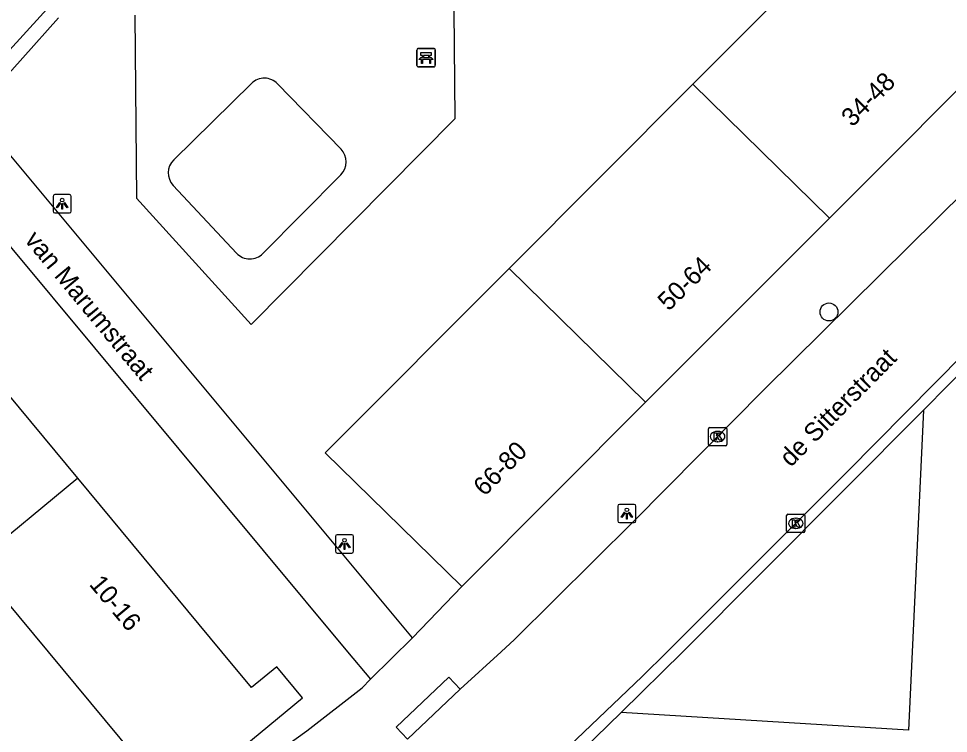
# Model space of a CAD drawing. Extents: x 159888 to 160757, y 384031 to 384746.
# Drawn here: x 160339 to 160389.7, y 384245.5 to 384284.5 of the extents above; entities that cross this region are included whole.
import ezdxf

# ---------------------------------------------------------------- set-up
doc = ezdxf.new("R2010")
doc.units = 0
for name, color, linetype in [('IMGEO_Bank', 7, 'Continuous'), ('IMGEO_Boom', 7, 'Continuous'), ('IMGEO_Kolk', 7, 'Continuous'), ('IMGEO_Lichtpunt', 7, 'Continuous'), ('IMGEO_Openbare_ruimte_label', 7, 'Continuous'), ('IMGEO_Pand', 7, 'Continuous'), ('IMGEO_Pand_nummerreeks', 7, 'Continuous'), ('IMGEO_Rijbaan_lokaal_open', 7, 'Continuous'), ('IMGEO_Voetpad_halfverhard', 7, 'Continuous'), ('IMGEO_Voetpad_open', 7, 'Continuous')]:
    doc.layers.add(name, color=color, linetype=linetype)

msp = doc.modelspace()

# ---------------------------------------------------------------- linework, layer by layer
at = {"layer": 'IMGEO_Bank'}
for p, q in [((160360.748, 384281.983), (160360.748, 384282.824)), ((160360.748, 384282.824), (160360.748, 384281.983)), ((160360.823, 384282.908), (160361.664, 384282.908)), ((160361.664, 384282.908), (160360.823, 384282.908)), ((160361.748, 384282.833), (160361.748, 384281.992)), ((160361.748, 384281.992), (160361.748, 384282.833)), ((160361.445, 384282.306), (160361.052, 384282.306)), ((160361.057, 384282.414), (160361.057, 384282.52)), ((160361.101, 384282.52), (160361.101, 384282.414)), ((160361.389, 384282.526), (160361.107, 384282.526)), ((160361.107, 384282.408), (160361.389, 384282.408)), ((160361.395, 384282.414), (160361.395, 384282.52)), ((160361.439, 384282.52), (160361.439, 384282.414)), ((160361.673, 384281.908), (160360.832, 384281.908)), ((160360.832, 384281.908), (160361.673, 384281.908))]:
    msp.add_line(p, q, dxfattribs=at)
for points in [[(160360.995, 384282.306), (160360.853, 384282.306), (160360.965, 384282.408), (160361.051, 384282.408)], [(160361.051, 384282.526), (160360.965, 384282.526), (160360.965, 384282.687), (160361.528, 384282.687), (160361.528, 384282.526), (160361.445, 384282.526)], [(160361.045, 384282.299), (160361.045, 384282.092), (160361.002, 384282.092), (160361.002, 384282.299)], [(160361.445, 384282.408), (160361.528, 384282.408), (160361.64, 384282.306), (160361.501, 384282.306)], [(160361.495, 384282.299), (160361.495, 384282.092), (160361.451, 384282.092), (160361.451, 384282.299)]]:
    msp.add_lwpolyline(points, dxfattribs=at)
for centre, radius, start, end in [((160360.826, 384282.83), 0.0779, 92.4484, 184.2845), ((160360.826, 384282.83), 0.0779, 92.4484, 184.2845), ((160361.67, 384282.83), 0.0779, 2.4484, 94.2845), ((160361.67, 384282.83), 0.0779, 2.4484, 94.2845), ((160360.995, 384282.299), 0.00671, 2.8957, 87.1043), ((160361.052, 384282.299), 0.00671, 92.8957, 177.1043), ((160361.05, 384282.519), 0.00671, 2.8957, 87.1043), ((160361.05, 384282.415), 0.00671, 272.8957, 357.1043), ((160361.107, 384282.519), 0.00671, 92.8957, 177.1043), ((160361.107, 384282.415), 0.00671, 182.8957, 267.1043), ((160361.389, 384282.519), 0.00671, 2.8957, 87.1043), ((160361.389, 384282.415), 0.00671, 272.8957, 357.1043), ((160361.446, 384282.519), 0.00671, 92.8957, 177.1043), ((160361.446, 384282.415), 0.00671, 182.8957, 267.1043), ((160361.444, 384282.299), 0.00671, 2.8957, 87.1043), ((160361.501, 384282.299), 0.00671, 92.8957, 177.1043), ((160360.826, 384281.986), 0.0779, 182.4484, 274.2845), ((160360.826, 384281.986), 0.0779, 182.4484, 274.2845), ((160361.67, 384281.986), 0.0779, 272.4484, 4.2845), ((160361.67, 384281.986), 0.0779, 272.4484, 4.2845)]:
    msp.add_arc(centre, radius, start, end, dxfattribs=at)
at = {"layer": 'IMGEO_Boom'}
msp.add_circle((160383.226, 384268.536), 0.489, dxfattribs=at)
at = {"layer": 'IMGEO_Kolk'}
for p, q in [((160376.649, 384261.31), (160376.649, 384262.162)), ((160376.724, 384262.236), (160377.576, 384262.236)), ((160377.137, 384262.016), (160377.162, 384262.016)), ((160377.65, 384262.162), (160377.65, 384261.31)), ((160377.576, 384261.236), (160376.724, 384261.236)), ((160377.16, 384261.456), (160377.135, 384261.456)), ((160380.991, 384257.501), (160381.843, 384257.501)), ((160380.916, 384256.575), (160380.916, 384257.427)), ((160381.404, 384257.281), (160381.429, 384257.281)), ((160381.917, 384257.427), (160381.917, 384256.575)), ((160381.843, 384256.501), (160380.991, 384256.501)), ((160381.427, 384256.721), (160381.402, 384256.721))]:
    msp.add_line(p, q, dxfattribs=at)
for points in [[(160376.649, 384261.31), (160376.649, 384262.162)], [(160376.724, 384262.236), (160377.576, 384262.236)], [(160377.65, 384262.162), (160377.65, 384261.31)], [(160376.97, 384261.936), (160377.093, 384261.936), (160377.093, 384261.785), (160377.223, 384261.936), (160377.387, 384261.936), (160377.241, 384261.785), (160377.394, 384261.536), (160377.242, 384261.536), (160377.157, 384261.7), (160377.093, 384261.633), (160377.093, 384261.536), (160376.97, 384261.536), (160376.97, 384261.936)], [(160377.576, 384261.236), (160376.724, 384261.236)], [(160380.991, 384257.501), (160381.843, 384257.501)], [(160380.916, 384256.575), (160380.916, 384257.427)], [(160381.237, 384257.201), (160381.36, 384257.201), (160381.36, 384257.05), (160381.49, 384257.201), (160381.654, 384257.201), (160381.508, 384257.05), (160381.661, 384256.801), (160381.509, 384256.801), (160381.424, 384256.965), (160381.36, 384256.898), (160381.36, 384256.801), (160381.237, 384256.801), (160381.237, 384257.201)], [(160381.917, 384257.427), (160381.917, 384256.575)], [(160381.843, 384256.501), (160380.991, 384256.501)]]:
    msp.add_lwpolyline(points, dxfattribs=at)
for centre, start, end in [((160376.726, 384262.16), 91.552, 178.448), ((160376.726, 384262.16), 91.552, 178.448), ((160377.574, 384262.16), 1.552, 88.448), ((160377.574, 384262.16), 1.552, 88.448), ((160376.726, 384261.312), 181.552, 268.448), ((160376.726, 384261.312), 181.552, 268.448), ((160377.574, 384261.312), 271.552, 358.448), ((160377.574, 384261.312), 271.552, 358.448), ((160380.993, 384257.425), 91.552, 178.448), ((160380.993, 384257.425), 91.552, 178.448), ((160381.841, 384257.425), 1.552, 88.448), ((160381.841, 384257.425), 1.552, 88.448), ((160380.993, 384256.577), 181.552, 268.448), ((160380.993, 384256.577), 181.552, 268.448), ((160381.841, 384256.577), 271.552, 358.448), ((160381.841, 384256.577), 271.552, 358.448)]:
    msp.add_arc(centre, 0.0765, start, end, dxfattribs=at)
for centre, major_axis, ratio, start_param, end_param in [((160377.136, 384261.736), (-0.387, 0.002), 0.722429, 4.712389, 7.853982), ((160377.161, 384261.736), (-0.39, 0.002), 0.717154, 1.570796, 4.712389), ((160381.403, 384257.001), (-0.387, 0.002), 0.722429, 4.712389, 7.853982), ((160381.428, 384257.001), (-0.39, 0.002), 0.717154, 1.570796, 4.712389)]:
    msp.add_ellipse(centre, major_axis=major_axis, ratio=ratio, start_param=start_param, end_param=end_param, dxfattribs=at)
at = {"layer": 'IMGEO_Lichtpunt'}
for p, q in [((160340.892, 384274.841), (160340.892, 384274.034)), ((160340.892, 384274.841), (160340.892, 384274.034)), ((160341.794, 384274.936), (160340.986, 384274.936)), ((160341.794, 384274.936), (160340.986, 384274.936)), ((160341.888, 384274.034), (160341.888, 384274.841)), ((160341.888, 384274.034), (160341.888, 384274.841)), ((160340.986, 384273.94), (160341.794, 384273.94)), ((160340.986, 384273.94), (160341.794, 384273.94)), ((160372.602, 384258.037), (160371.794, 384258.037)), ((160372.602, 384258.037), (160371.794, 384258.037)), ((160371.7, 384257.942), (160371.7, 384257.135)), ((160371.7, 384257.942), (160371.7, 384257.135)), ((160372.696, 384257.135), (160372.696, 384257.942)), ((160372.696, 384257.135), (160372.696, 384257.942)), ((160371.794, 384257.041), (160372.602, 384257.041)), ((160371.794, 384257.041), (160372.602, 384257.041)), ((160356.295, 384256.285), (160356.295, 384255.478)), ((160356.295, 384256.285), (160356.295, 384255.478)), ((160357.197, 384256.38), (160356.389, 384256.38)), ((160357.197, 384256.38), (160356.389, 384256.38)), ((160357.291, 384255.478), (160357.291, 384256.285)), ((160357.291, 384255.478), (160357.291, 384256.285)), ((160356.389, 384255.384), (160357.197, 384255.384)), ((160356.389, 384255.384), (160357.197, 384255.384))]:
    msp.add_line(p, q, dxfattribs=at)
for points in [[(160341.266, 384274.505), (160341.305, 384274.477), (160341.117, 384274.215), (160341.079, 384274.242), (160341.266, 384274.505)], [(160341.368, 384274.457), (160341.415, 384274.457), (160341.415, 384274.135), (160341.368, 384274.135), (160341.368, 384274.457)], [(160341.478, 384274.477), (160341.516, 384274.504), (160341.703, 384274.242), (160341.664, 384274.214), (160341.478, 384274.477)], [(160372.074, 384257.606), (160372.113, 384257.578), (160371.925, 384257.316), (160371.887, 384257.343), (160372.074, 384257.606)], [(160372.176, 384257.558), (160372.223, 384257.558), (160372.223, 384257.236), (160372.176, 384257.236), (160372.176, 384257.558)], [(160372.286, 384257.578), (160372.324, 384257.605), (160372.511, 384257.343), (160372.472, 384257.315), (160372.286, 384257.578)], [(160356.669, 384255.949), (160356.708, 384255.921), (160356.52, 384255.659), (160356.482, 384255.686), (160356.669, 384255.949)], [(160356.881, 384255.921), (160356.919, 384255.948), (160357.106, 384255.686), (160357.067, 384255.658), (160356.881, 384255.921)], [(160356.771, 384255.901), (160356.818, 384255.901), (160356.818, 384255.579), (160356.771, 384255.579), (160356.771, 384255.901)]]:
    msp.add_lwpolyline(points, dxfattribs=at)
for centre in [(160341.391, 384274.639), (160372.199, 384257.74), (160356.794, 384256.083)]:
    msp.add_circle(centre, 0.0994, dxfattribs=at)
for centre, start, end in [((160340.986, 384274.841), 90, 180), ((160340.986, 384274.841), 90, 180), ((160341.794, 384274.841), 0, 90), ((160341.794, 384274.841), 0, 90), ((160340.986, 384274.034), 180, 270), ((160340.986, 384274.034), 180, 270), ((160341.794, 384274.034), 270, 0), ((160341.794, 384274.034), 270, 360), ((160371.794, 384257.942), 90, 180), ((160371.794, 384257.942), 90, 180), ((160372.602, 384257.942), 0, 90), ((160372.602, 384257.942), 0, 90), ((160371.794, 384257.135), 180, 270), ((160371.794, 384257.135), 180, 270), ((160372.602, 384257.135), 270, 0), ((160372.602, 384257.135), 270, 360), ((160356.389, 384256.285), 90, 180), ((160356.389, 384256.285), 90, 180), ((160357.197, 384256.285), 0, 90), ((160357.197, 384256.285), 0, 90), ((160356.389, 384255.478), 180, 270), ((160356.389, 384255.478), 180, 270), ((160357.197, 384255.478), 270, 0), ((160357.197, 384255.478), 270, 360)]:
    msp.add_arc(centre, 0.0946, start, end, dxfattribs=at)
at = {"layer": 'IMGEO_Pand'}
for points in [[(160385.826, 384291.012), (160375.799, 384280.956)], [(160383.258, 384273.657), (160393.291, 384283.706)], [(160375.799, 384280.956), (160365.773, 384270.9)], [(160375.799, 384280.956), (160383.258, 384273.657)], [(160373.224, 384263.607), (160383.258, 384273.657)], [(160342.239, 384259.468), (160332.771, 384270.87), (160332.038, 384270.121), (160330.555, 384271.85), (160325.333, 384267.508), (160326.868, 384265.704), (160327.269, 384266.034), (160336.616, 384254.819)], [(160365.773, 384270.9), (160355.746, 384260.844), (160363.191, 384253.558)], [(160373.224, 384263.607), (160365.773, 384270.9)], [(160363.191, 384253.558), (160373.224, 384263.607)], [(160342.239, 384259.468), (160336.616, 384254.819)], [(160336.616, 384254.819), (160340.632, 384250), (160346.039, 384243.463), (160345.684, 384243.17), (160347.147, 384241.401), (160354.506, 384247.489), (160353.105, 384249.183), (160351.726, 384248.043), (160350.101, 384250), (160342.239, 384259.468)]]:
    msp.add_lwpolyline(points, dxfattribs=at)
at = {"layer": 'IMGEO_Rijbaan_lokaal_open'}
for points in [[(160319.303, 384267.551), (160320.163, 384268.187), (160325.613, 384272.322), (160329.833, 384275.348), (160333.576, 384278.079), (160335.984, 384279.983), (160336.104, 384280.105), (160336.716, 384280.731), (160338.331, 384282.617), (160345.01, 384289.972), (160361.399, 384308.557), (160367.398, 384315.345), (160372.06, 384320.608), (160386.091, 384336.349), (160387.995, 384338.559)], [(160415.801, 384300.405), (160412.696, 384297.247), (160409.504, 384293.847), (160396.973, 384281.372), (160379.726, 384264.338), (160372.559, 384257.094), (160366.063, 384250.659), (160365.342, 384250), (160363.109, 384247.959)], [(160346.326, 384226.816), (160346.553, 384226.989), (160354.699, 384232.863), (160360.784, 384237.351), (160361.189, 384237.649), (160363.689, 384239.781), (160364.647, 384240.62), (160366.673, 384242.576), (160373.037, 384248.641), (160374.399, 384250), (160384.224, 384259.805), (160390.609, 384266.27), (160401.354, 384277.085), (160418.41, 384294.276)], [(160363.109, 384247.959), (160360.237, 384245.231)]]:
    msp.add_lwpolyline(points, dxfattribs=at)
at = {"layer": 'IMGEO_Voetpad_halfverhard'}
for points in [[(160345.355, 384284.72), (160345.439, 384274.748), (160351.699, 384267.85), (160362.837, 384279.095), (160362.772, 384285.007)], [(160347.476, 384276.837), (160351.726, 384281.003)], [(160353.143, 384280.985), (160356.604, 384277.418)], [(160356.597, 384276.018), (160352.346, 384271.723)], [(160350.905, 384271.743), (160347.446, 384275.44)], [(160388.378, 384263.174), (160387.768, 384250), (160387.57, 384245.716), (160371.882, 384246.688)]]:
    msp.add_lwpolyline(points, dxfattribs=at)
for centre, radius, start, end in [((160352.426, 384280.287), 1.001, 44.1995, 134.3449), ((160355.885, 384276.722), 1.001, 315.3369, 44.0901), ((160348.174, 384276.123), 0.999, 134.376, 223.1635), ((160351.635, 384272.425), 0.999, 223.0474, 315.3623)]:
    msp.add_arc(centre, radius, start, end, dxfattribs=at)
at = {"layer": 'IMGEO_Voetpad_open'}
for points in [[(160336.483, 384279.562), (160337.275, 384280.219), (160341.199, 384284.583)], [(160360.504, 384250.764), (160336.483, 384279.562)], [(160333.927, 384277.642), (160356.959, 384250), (160358.209, 384248.5)], [(160388.378, 384263.174), (160391.104, 384265.938)], [(160371.882, 384246.688), (160375.258, 384250), (160388.378, 384263.174)], [(160360.504, 384250.764), (160363.191, 384253.558)], [(160358.209, 384248.5), (160360.504, 384250.764)], [(160340.225, 384235.253), (160354.731, 384245.687), (160357.767, 384248.02), (160358.209, 384248.5)], [(160363.109, 384247.959), (160362.49, 384248.612), (160359.618, 384245.884), (160360.237, 384245.231)], [(160369.777, 384244.623), (160371.882, 384246.688)]]:
    msp.add_lwpolyline(points, dxfattribs=at)

# ---------------------------------------------------------------- texts
at = {"layer": 'IMGEO_Openbare_ruimte_label'}
for s, rotation, p in [('van Marumstraat', 309.7249, (160339.298, 384272.441)), ('de Sitterstraat', 45.3242, (160381.139, 384260.027))]:
    msp.add_text(s, height=1, rotation=rotation, dxfattribs=at).set_placement(p)
at = {"layer": 'IMGEO_Pand_nummerreeks'}
for s, rotation, p in [('34-48', 45, (160384.502, 384278.584)), ('50-64', 44.7878, (160374.483, 384268.542)), ('66-80', 45.3177, (160364.433, 384258.437)), ('10-16', 309.773, (160342.825, 384253.661))]:
    msp.add_text(s, height=1, rotation=rotation, dxfattribs=at).set_placement(p)

doc.saveas('drawing.dxf')
